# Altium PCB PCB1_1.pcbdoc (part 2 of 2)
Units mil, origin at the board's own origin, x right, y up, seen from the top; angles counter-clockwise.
Board outline 2576.88 x 4443.16 mil, 6 copper layers (Top Layer, Inner1, Inner2, Inner3, Inner4, Bottom Layer); 86 components, 97 nets, 400 pads, 188 vias.
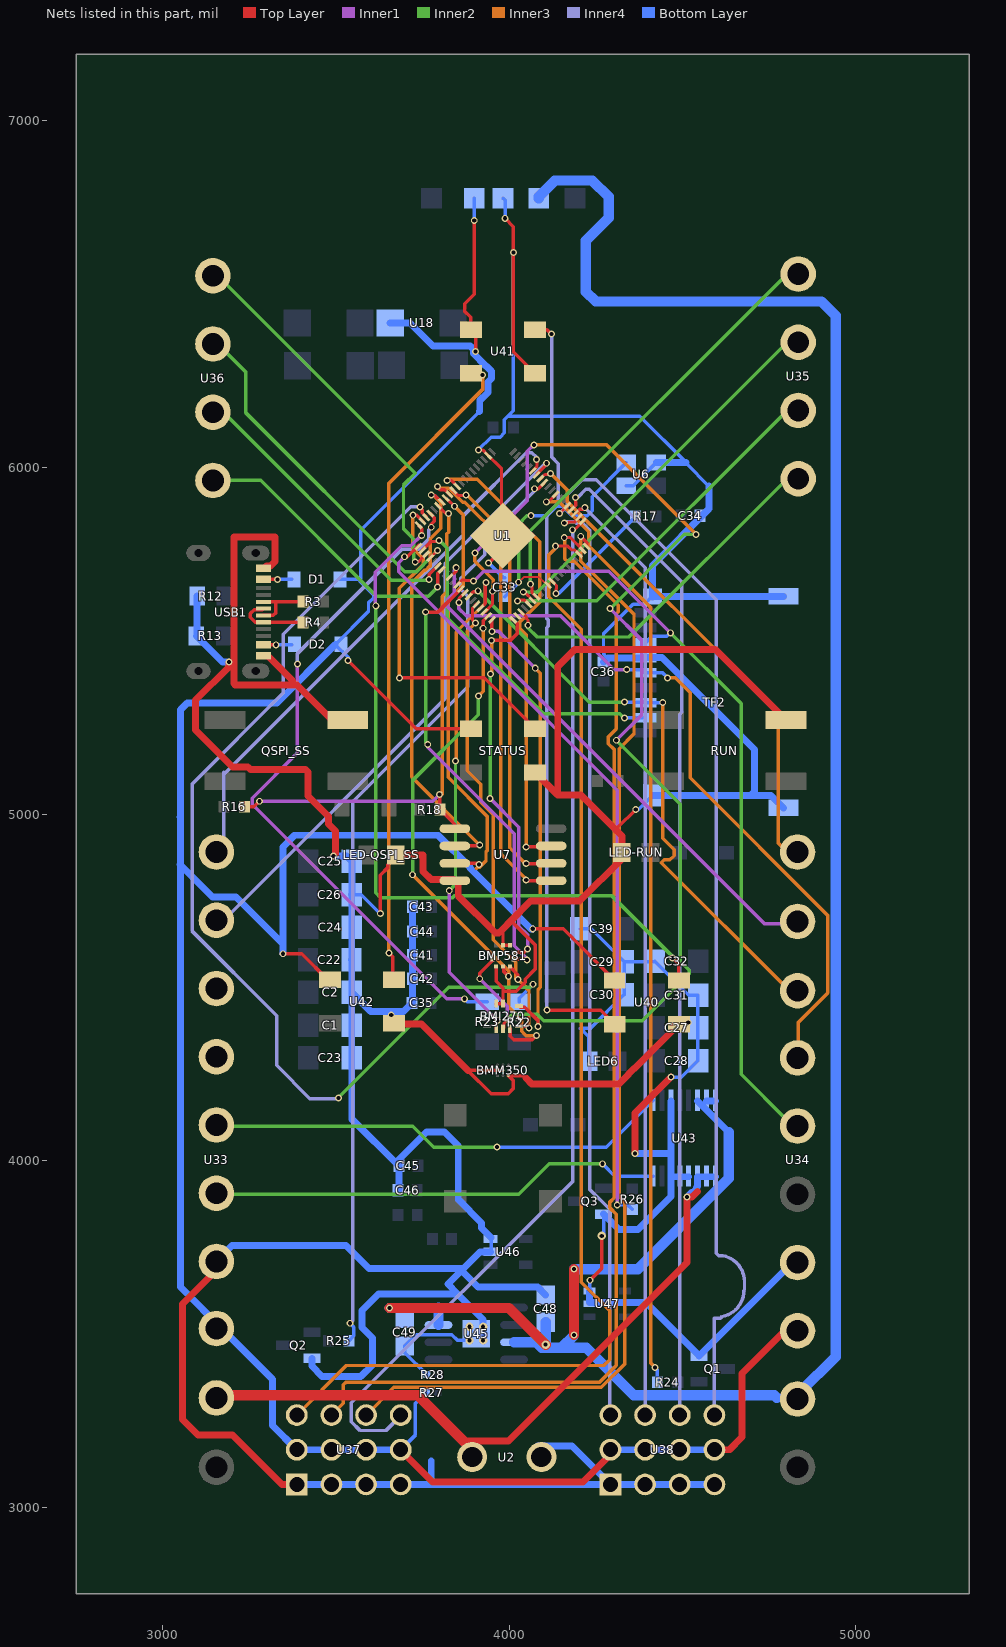
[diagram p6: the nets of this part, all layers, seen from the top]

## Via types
v1: diameter 20, hole 12.01, Top Layer to Bottom Layer, 175 vias
v2: diameter 24.02, hole 12.01, Top Layer to Bottom Layer, 8 vias
v3: diameter 24, hole 12, Top Layer to Bottom Layer, 4 vias
v4: diameter 20, hole 12, Top Layer to Bottom Layer, 1 vias

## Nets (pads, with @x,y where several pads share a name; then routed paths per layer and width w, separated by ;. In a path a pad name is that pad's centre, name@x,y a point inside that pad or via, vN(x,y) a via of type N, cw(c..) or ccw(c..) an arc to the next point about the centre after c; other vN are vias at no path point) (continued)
$5N18524: U40.2 U41.4 | length 2242.1
  Top Layer w10: U41.4@4073.4,6398.16 4108.78,6398.16 v1(4121.96,6384.98) ; v1(4108.42,4434.56) 4263.97,4434.56 U40.2@4304.36,4394.17
  Inner4 w10: v1(4108.42,4434.56) 4108.42,5538.19 4111.88,5541.64 4111.88,5560.68 4108.42,5564.14 4108.42,5863.22 4141.88,5896.67 4141.88,6010.91 4121.96,6030.83 v1(4121.96,6384.98)
$5N18586: U41.2 U42.4 | length 1863.2
  Top Layer w10: v1(3652.88,4599.16) 3663.4,4588.64 U42.4@3663.4,4520.16
  Inner3 w10: v1(3652.88,4599.16) 3652.88,5955.16 3922.88,6225.16 v1(3922.88,6267.16)
$5N24177: D1.2 USB1.2 | length 81.7
  Top Layer w10: USB1.2@3290.39,5677.65 3330.4,5677.65 v1(3330.88,5677.16)
  Bottom Layer w10: v1(3330.88,5677.16) D1.2@3371.89,5677.16
$5N24251: D2.2 USB1.11 | length 79.9
  Top Layer w10: USB1.11@3290.39,5488.67 v1(3327.29,5488.67)
  Bottom Layer w10: v1@3328.88,5489.16 D2.2@3371.89,5489.16
+5V: D1.1 D2.1 pad.4 R27.2 STATUS.1 U18.2 U33.3 U34.8 U37.2 U37.5 U37.8 U37.11 U38.2 U38.5 U38.8 U38.11 U40.1 U41.1 U42.1 | length 9155
  Top Layer w10: v1(3346.88,4597.16) 3401.36,4597.16 U42.1@3478.36,4520.16 ; v1(3534.88,5443.16) 3731.89,5246.16 STATUS.1@3889.36,5246.16 ; v1(3898.88,6713.16) 3898.88,6499.69 3871.88,6472.68 3871.88,6450.17 3888.36,6433.68 3888.36,6398.16 3902.89,6383.63 v1(3902.89,6334.61) ; v1(4067.84,4669.16) 4155.36,4669.16 U40.1@4304.36,4520.16
  Top Layer w20: U37.11@3686.88,3148.16 3703.88,3148.16 3778.88,3073.16 4213.17,3073.16 4291.88,3151.88 U38.2@4291.88,3180.16 ; U38.11@4591.88,3166.16 4634.88,3166.16 4671.88,3203.16 4671.88,3385.76 U34.8@4801.88,3515.76
  Bottom Layer w10: D1.1@3511.98,5677.21 3563.83,5677.21 3571.88,5669.16 ; v1(3534.88,5443.16) 3534.88,5452.15 3497.88,5489.16 3593.9,5585.18 3593.9,5609.85 3608.88,5624.84 3608.88,5632.15 3571.88,5669.16 ; U37.11@3686.88,3166.16 3729.36,3208.64 3729.36,3300.68 R27.2@3759.84,3331.16 ; v1@3898.31,6333.09 3901.36,6333.09 v1(3902.89,6334.61) ; v1(3898.88,6713.16) pad.4@3898.88,6777.16 ; 3913.43,6161.16 3571.88,5819.6 3571.88,5669.16
  Bottom Layer w20: 3049.72,4854.74 3050.88,4853.58 ; 3049.72,4991.77 3050.88,4992.93 ; v1(3346.88,4597.16) 3346.88,4625.58 ; D2.1@3497.88,5489.16 3329.88,5321.16 3070.88,5321.16 3050.88,5301.16 3050.88,4992.93 ; U18.2@3656.33,6417.16 3713.43,6417.16 3780.08,6350.52 3887.42,6350.52 3896.79,6341.15 v1@3896.79,6334.61 ; U37.11@3686.88,3166.16 U37.8@3586.88,3166.16 U37.5@3486.88,3166.16 U37.2@3386.88,3166.16 3316.88,3236.16 3316.88,3369.46 3176.88,3509.46 3050.88,3635.46 3050.88,4853.58 ; v1@3896.79,6328.51 3932.16,6293.15 3933.65,6293.15 3948.87,6277.92 3948.87,6256.4 3938.79,6246.32 3938.79,6217.07 3914.88,6193.16 3914.88,6162.61 3913.43,6161.16 ; v1(4067.84,4669.16) 4062.14,4669.16 3886.9,4844.4 3886.9,4847.15 3794.88,4939.16 3380.88,4939.16 3346.88,4905.16 3346.88,4625.58 ; U38.2@4291.88,3166.16 U38.5@4391.88,3166.16 U38.8@4491.88,3166.16 U38.11@4591.88,3166.16 ; 3050.88,4853.58 3143.59,4760.87 3211.59,4760.87 3346.88,4625.58 ; 3050.88,4853.58 3050.88,4992.93
ADC0: R24.1 U1.49 | length 2731.5
  Top Layer w9: v1(4106.88,5901.16) 4113.29,5901.16 U1.49@4135.21,5923.08
  Inner3 w10: v1(4106.88,5901.16) 4143.4,5901.16 4229.21,5815.35 4229.21,5774.84 4408.88,5595.16 4408.88,3415.16 v1(4420.88,3403.16)
  Bottom Layer w10: v1(4420.88,3403.16) 4427.22,3396.82 R24.1@4427.22,3361.16
ADC1: R25.1 U1.52 | length 2743.5
  Top Layer w9: v1(4073.25,5938.79) 4084.11,5938.79 U1.52@4101.8,5956.48
  Inner4 w10: v1(3540.88,3531.16) 3547.89,3538.17 3547.89,5035.75 3879.88,5367.73 3879.88,5629.05 3860.41,5648.52 3860.41,5680.03 3928.87,5748.49 3928.87,5788.41 v1@4079.25,5938.79
  Bottom Layer w10: R25.1@3537.85,3480.64 3551.85,3494.64 3551.85,3520.19 v1(3540.88,3531.16)
ADC2: U1.53 U34.1 | length 1410.2
  Top Layer w9: U1.53@4090.67,5967.62 4102.83,5979.79 4115.51,5979.79 v1(4118.88,5983.16)
  Inner3 w10: v1(4118.88,5983.16) 4167.89,5934.15 4167.89,5901.84 4775.78,5293.95 4775.78,4916.66 U34.1@4801.88,4890.56
ADC3: U1.54 U33.9 | length 1752.8
  Top Layer w9: U1.54@4079.53,5980.76 4107.89,6009.12 v1@4107.89,6014.38
  Inner4 w10: U33.9@3172.88,4690.56 3815.88,5333.56 3815.88,5724.37 v1@4103.89,6012.38
  other v1: 4107.89,6012.38
ADC4: U1.55 U33.10 | length 1582.5
  Top Layer w9: U1.55@4068.39,5991.89 4080.56,6004.07 4080.56,6013.77 4078.98,6015.35 v1@4078.98,6025.26
  Inner4 w10: U33.10@3176.88,4896.56 3176.88,5115.48 ; 3176.88,5121.48 3176.88,5115.48 ; 3867.87,5806.47 3176.88,5115.48 ; 3867.87,5812.47 3867.87,5861.63 4049.5,6043.26 4064.98,6043.26 v1@4078.98,6029.26
  other v1: 4078.98,6023.26
BUZ: R26.1 U1.1 | length 2242.8
  Top Layer w10: v1(3697.83,5742.73) 3705.88,5742.73 U1.1@3739.47,5776.33
  Inner1 w10: v1(3697.83,5742.73) 3680.88,5725.79 3680.88,5699.16 4311.58,5068.46 v1(4311.58,3872.38)
  Bottom Layer w10: v1(4311.58,3872.38) 4342,3872.38 R26.1@4354.88,3859.5
CLK: TF2.5 U1.13 U34.4 | length 2080.7
  Top Layer w9: v1@3854.88,5612.28 3854.88,5622.48 U1.13@3873.1,5640.7
  Inner1 w10: v1(3854.88,5610.28) 3854.88,5592.83 3875.57,5572.15 4147.9,5572.15 4302.88,5417.16 v1(4338.88,5417.16)
  Inner3 w10: v1(4456.88,5393.16) 4478.88,5393.16 4521.87,5350.18 4521.87,5104.66 4918.88,4707.64 4918.88,4483.94 4833.88,4398.94 U34.4@4833.88,4290.01
  Bottom Layer w10: v1(4338.88,5417.16) 4383.72,5417.16 TF2.5@4393.07,5407.81 4442.23,5407.81 v1(4456.88,5393.16)
CS: U1.9 U34.2 | length 1492.4
  Top Layer w10: 3840.73,5695.41 3846.88,5701.56 v1(3846.88,5711.16)
  Inner1 w10: v1@3846.88,5709.16 3840.88,5703.16 3840.88,5638.04 3821.89,5619.05 3821.89,5598.15 4736.34,4683.71 U34.2@4795.88,4683.71
GND: BMI270.6 BMI270.7 BMM350.B1 BMM350.B2 BMM350.C3 BMP581.3 BMP581.8 BMP581.9 C1.1 C2.1 C22.1 C23.1 C24.1 C25.1 C26.1 C27.1 C28.1 C29.1 C30.1 C31.1 C32.2 C33.1 C34.1 C35.2 C36.1 C39.2 C41.2 C42.1 C43.2 C44.1 C45.2 C46.1 C48.2 C49.2 LED6.2 LED-QSPI_SS.2 LED-RUN.2 pad.3 Q1.2 Q2.2 Q3.2 QSPI_SS.2 R12.2 R13.2 R28.2 RUN.2 STATUS.3 TF2.6 TF2.10 TF2.11 TF2.12 TF2.13 U1.62 U1.81 U2.2 U6.2 U6.4 U7.4 U33.4 U34.7 U37.1 U37.4 U37.7 U37.10 U38.1 U38.4 U38.7 U38.10 U40.3 U41.3 U42.3 U43.4 U43.5 U43.6 U43.11 U45.9 U46.2 U46.3 U47.2 U47.3 USB1.1 USB1.12 | length 21390.6
  Top Layer w9: v1(3910.88,6051.16) 3923.19,6051.16 U1.62@3935.22,6039.13 ; U1.62@3934.61,6039.13 U1.62@3935.22,6039.13 ; U1.81@3977.88,5809.16 3977.88,5996.47 U1.62@3935.22,6039.13
  Top Layer w10: v1(3627.88,4713.16) 3627.88,4823.99 3650.03,4846.14 3650.03,4854.3 3672.6,4876.87 LED-QSPI_SS.2@3672.6,4882.49 ; v1(3940.34,5724.61) 3981.88,5766.16 U1.81@3981.88,5803.16 ; BMI270.7@3962.19,4453.38 BMI270.6@3981.88,4453.38 3981.88,4488.49 ; BMP581.3@3962.2,4560.45 3962.2,4517.85 3981.88,4498.16 3981.88,4488.49 ; BMM350.B2@3981.88,4261.16 BMM350.B1@3966.13,4261.16 3882.19,4261.16 3881,4259.97 3947.81,4193.16 3996.88,4193.16 4010.88,4207.16 4010.88,4232.16 BMM350.C3@3997.63,4245.41 BMM350.C3@3997.22,4245.83 ; 3981.89,4669.18 BMP581.9@3981.89,4621.87 BMP581.8@4001.57,4621.87 ; v1(3987.88,6719.16) 4011.88,6695.16 v1(4011.88,6620.84) 4011.88,6333.69 U41.3@4073.4,6272.17 ; BMM350.C3@3998.46,4245.41 4040.63,4245.41 4047.88,4238.16 ; 4005.09,4692.38 4074.88,4622.58 4074.88,4553.16 4045.87,4524.15 4045.87,4514.47 4019.89,4488.49 3981.88,4488.49 ; v1(4232.88,3655.16) 4266.89,3689.17 v2(4266.89,3783.16) ; 4300.2,4961.84 4313.57,4961.84 v1(4364.88,5013.16)
  Top Layer w20: U33.4@3176.88,3706.31 3056.88,3586.31 3056.88,3253.16 3101.88,3208.16 3201.88,3208.16 3343.88,3066.16 U37.1@3386.88,3066.16 ; v1(3190.88,5439.16) 3190.88,5425.16 3094.88,5329.16 3094.88,5243.16 3201.89,5136.16 3245.39,5136.16 3253.32,5128.23 3411.81,5128.23 3418.88,5121.16 3418.88,5052.67 3478.88,4992.67 3478.88,4971.16 3498.88,4951.16 3498.88,4885.16 v1(3492.88,4879.16) ; USB1.12@3290.39,5457.18 3303.05,5457.18 3374.56,5385.66 3374.56,5373 ; USB1.1@3290.39,5709.15 3291.39,5708.15 3299.04,5715.8 3311.52,5715.8 3324.09,5728.37 3324.09,5799.95 3205.67,5799.95 3205.67,5376.37 3209.04,5373 3374.56,5373 ; QSPI_SS.2@3534.05,5271.74 3488.3,5271.74 3387.04,5373 3374.56,5373 ; U42.3@3663.4,4394.17 3746.81,4394.17 3881,4259.97 ; LED-QSPI_SS.2@3672.6,4882.49 3750.94,4882.49 3750.94,4835.11 3774.88,4811.16 U7.4@3839.9,4811.16 ; U7.4@3842.9,4808.16 3852.87,4798.2 3852.87,4764.47 3960.89,4656.45 3969.16,4656.45 3981.89,4669.18 4005.09,4692.38 4061.87,4749.16 4202.88,4749.16 4324.9,4871.17 4324.9,4937.15 4300.2,4961.84 4207.37,5054.68 4139.89,5054.68 ; U1.81@3971.88,5803.16 U1.81@3976.88,5808.16 ; 4047.88,4238.16 4064.88,4221.16 4316.4,4221.16 4344.1,4248.86 4344.1,4250.86 4359.32,4266.08 4361.32,4266.08 U40.3@4489.4,4394.17 U40.3@4489.4,4396.17 ; STATUS.3@4074.4,5120.17 4139.89,5054.68 ; v1(4362.88,4021.16) 4362.88,4137.16 v1(4466.88,4241.16) ; RUN.2@4799.05,5271.74 4595.63,5475.16 4188.88,5475.16 4139.89,5426.17 4139.89,5054.68
  Bottom Layer w10: C26.1@3545.21,4767.96 3573.08,4767.96 v1(3627.88,4713.16) ; R28.2@3761.84,3383.16 3698.88,3446.12 C49.2@3698.88,3465.79 3731.54,3498.44 3833.91,3498.44 3850.89,3481.47 v3(3885.2,3481.47) ; v1(3910.88,6051.16) 3947.64,6087.91 3973.49,6087.91 3985.52,6099.95 3985.52,6137.46 3995.88,6147.82 ; v3(3924.57,3481.47) v3(3924.57,3520.84) ; v1(3940.34,5724.61) 3982.23,5682.72 C33.1@3986.88,5682.72 ; U46.2@3947.7,3741.16 U46.3@3947.7,3778.56 ; pad.3@3981.88,6777.16 3987.88,6771.16 v1(3987.88,6719.16) ; v1(4011.88,6620.84) 4011.88,6163.82 3995.88,6147.82 ; C39.2@4204.78,4669.11 4236.54,4669.11 C29.1@4331.23,4574.41 ; LED6.2@4229.53,4287.16 4229.53,4357.56 4204.22,4382.88 4235.23,4382.88 C30.1@4330.77,4478.41 4331.23,4478.87 C29.1@4331.23,4574.41 ; U47.3@4231.7,3626.57 4231.7,3653.98 v1(4232.88,3655.16) ; v2(4266.89,3783.16) 4272.25,3788.52 Q3.2@4272.25,3845.76 ; C36.1@4278.93,5445.76 4278.93,5455.76 4271.86,5462.84 4271.86,5520.64 4357.02,5605.8 4390.39,5605.8 TF2.10@4412.75,5628.16 ; U6.2@4337.57,5947.7 4357.26,5947.7 U6.4@4424.19,6014.63 ; v1(4364.88,5013.16) 4372.43,5013.16 TF2.13@4412.75,5053.48 ; v1(4466.88,4241.16) 4496.79,4241.16 4543.58,4287.96 4543.58,4383.16 4543.58,4477.16 4518.18,4477.16 C32.2@4420.18,4575.16 4419.44,4574.41 C29.1@4331.23,4574.41 ; 4510.12,6012.63 4576.11,5946.63 ; 4510.12,6014.63 4376.92,6147.82 3995.88,6147.82
  Bottom Layer w20: R12.2@3099.51,5629.16 3099.51,5516.57 R13.2@3097.19,5514.25 3172.28,5439.16 v1(3190.88,5439.16) ; U33.4@3154.88,3709.46 3200.59,3755.16 3528.88,3755.16 3595.08,3688.96 3867.92,3688.96 ; U37.1@3386.88,3066.16 U37.4@3486.88,3066.16 U37.7@3586.88,3066.16 U37.10@3686.88,3066.16 3774.98,3066.16 ; Q2.2@3430.25,3429.76 3430.25,3407.76 3460.25,3377.76 3571.48,3377.76 3604.88,3411.16 3604.88,3488.82 3574.88,3518.82 3574.88,3567.5 3622.81,3615.43 3851.12,3615.43 ; v1(3492.88,4879.16) 3530.46,4879.16 C25.1@3545.66,4863.96 3545.66,4768.41 C26.1@3545.21,4767.96 3545.58,4767.58 C24.1@3545.58,4673.16 3545.58,4580.51 C22.1@3545.03,4579.96 3545.49,4579.5 C2.1@3545.49,4485.96 ; C46.1@3679.32,3915.16 3681.32,3917.16 C45.2@3681.32,3985.16 ; C43.2@3720.6,4732.6 3721.32,4731.87 C44.1@3721.32,4661.16 C41.2@3721.32,4593.16 C42.1@3721.32,4525.16 3721.32,4457.16 3695.32,4431.16 3600.29,4431.16 C2.1@3545.49,4485.96 ; 3774.88,3133.5 3774.88,3066.26 3774.98,3066.16 ; v3(3924.57,3520.84) 3924.57,3541.97 3851.12,3615.43 ; U46.2@3945.7,3737.16 3916.11,3737.16 3867.92,3688.96 ; U46.3@3947.7,3778.56 3919.99,3806.28 3919.99,3820.93 3852.88,3888.03 3852.88,4043.16 3812.88,4083.16 3761.32,4083.16 3681.32,4003.16 C45.2@3681.32,3985.16 ; U2.2@4081.88,3177.16 4180.88,3177.16 U38.1@4291.88,3066.16 ; C48.2@4104.88,3612.53 4082.25,3635.16 3910.3,3635.16 3862.21,3683.25 ; U47.3@4231.7,3624.56 4231.7,3591.16 4394.92,3591.16 Q1.2@4547.51,3438.56 ; C36.1@4271.86,5438.69 4278.93,5445.76 4284.29,5451.12 TF2.6@4393.07,5451.12 4394.52,5452.57 4441.11,5452.57 4707.56,5186.13 4707.56,5065.48 4695.56,5053.48 ; Q3.2@4272.25,3845.76 4316.85,3801.16 4370.88,3801.16 4466.49,3896.77 U43.6@4466.49,3953.71 ; v1(4362.88,4021.16) 4465.69,4021.16 4466.49,4021.96 ; TF2.13@4412.75,5053.48 4695.56,5053.48 ; TF2.10@4412.75,5626.16 TF2.10@4412.75,5628.16 ; U6.4@4424.19,6014.63 4510.12,6014.63 ; U43.11@4466.49,4172.61 4466.49,4021.96 ; U43.4@4517.68,3953.71 4492.08,3953.71 U43.6@4466.49,3953.71 ; Q1.2@4547.51,3436.56 4801.88,3690.93 U34.7@4801.88,3709.46 ; 4576.11,5946.63 4576.11,5881.14 4412.75,5717.77 TF2.10@4412.75,5628.16 ; U38.10@4591.88,3066.16 U38.7@4491.88,3066.16 U38.4@4391.88,3066.16 U38.1@4291.88,3066.16 ; TF2.12@4790.7,5018.04 4755.26,5053.48 4695.56,5053.48 ; TF2.11@4790.7,5628.28 4790.58,5628.16 TF2.10@4412.75,5628.16 ; C2.1@3545.49,4485.96 3545.49,4391.25 C1.1@3545.58,4391.16 C23.1@3545.58,4297.16 3545.58,4120.9 C45.2@3681.32,3985.16 ; 3774.98,3066.16 U38.1@4291.88,3066.16 ; 3851.12,3615.43 3822.75,3643.79 3862.21,3683.25 ; 3862.21,3683.25 3867.92,3688.96 ; U43.6@4466.49,3953.71 4466.49,4021.96
  other v1: 4516.35,4398.66 3659.47,4420.81
  other v3: 3885.2,3520.84
GPIO0: R23.1 U1.77 | length 2004.3
  Top Layer w10: U1.77@3771.88,5867.4 3784.05,5855.24 3784.05,5845.52 3774.88,5836.35 v1(3774.88,5827.72)
  Inner1 w10: v1(3388.88,5433.16) 3388.88,5176.84 3257.9,5045.85 3257.9,5028.47 3819.21,4467.16 v1(3870.88,4467.16)
  Inner4 w10: v1(3388.88,5433.16) 3388.88,5463.47 3689.13,5763.72 3737.02,5763.72 3768.28,5794.98 3768.28,5821.12 v1(3774.88,5827.72)
  Bottom Layer w10: v1(3870.88,4467.16) 3878.67,4459.38 R23.1@3936.54,4459.38
GPIO1: R22.1 U1.78 | length 3023
  Top Layer w9: v1(3742.88,5886.55) 3742.88,5884.55 3749.08,5878.35 3749.08,5868.93 U1.78@3761.75,5856.26
  Inner2 w10: v1(3506.88,4181.16) 3825.89,4500.17 4059.89,4500.17 v1(4068.88,4509.16)
  Inner4 w10: v1(3506.88,4181.16) 3504.88,4179.16 3424.88,4179.16 3328.88,4275.16 3328.88,4418.65 3084.72,4662.81 3084.72,5086.3 3348.27,5349.85 3348.27,5518.74 3716.08,5886.55 v1(3742.88,5886.55)
  Bottom Layer w10: R22.1@4028.95,4458.08 4028.95,4469.23 v1(4068.88,4509.16)
GPIO6: U1.3 U36.4 | length 1131.2
  Top Layer w9: v1@3728.79,5729.15 3738.84,5729.15 U1.3@3761.75,5752.06
  Inner2 w10: U36.4@3158.88,6553.44 3728.79,5983.54 3694.88,5949.64 3694.88,5823.57 3724.79,5793.67 v1@3724.79,5727.15
  other v1: 3728.79,5727.15
GPIO7: U1.4 U36.3 | length 1008.1
  Top Layer w9: U1.4@3770.88,5738.92 3792.88,5760.92 v1(3792.88,5761.16)
  Inner2 w10: U36.3@3176.88,6338.58 3239.05,6276.42 3239.05,6159 3698.83,5699.21 3733.36,5699.21 3751.78,5717.63 3751.78,5720.05 v1(3792.88,5761.16)
GPIO8: U1.6 U36.2 | length 841.6
  Top Layer w10: v1@3768.88,5679.16 3768.88,5691.77 U1.6@3795.15,5718.04
  Inner2 w10: U36.2@3176.88,6157.73 3659.45,5675.16 v1@3768.88,5675.16
  other v1: 3768.88,5677.16
GPIO9: U1.7 U36.1 | length 821.6
  Top Layer w10: v4@3792.88,5657.16 v4@3794.12,5658.4 ; 3793.75,5693.36 3793.12,5692.74 3793.12,5659.4 v4@3794.12,5658.4 ; v4@3794.12,5656.4 v4@3794.12,5658.4 ; 3794.12,5694.74 U1.7@3806.29,5706.9
  Inner2 w10: U36.1@3176.88,5962.88 3283.16,5962.88 3616.88,5629.16 3766.88,5629.16 v4(3792.88,5655.16)
GPIO13: BMP581.6 U1.12 | length 1293.8
  Top Layer w10: v1(3758.88,5583.16) 3794.29,5583.16 U1.12@3860.97,5649.84 ; BMP581.6@4012.59,4581.32 4048.72,4581.32 v1(4050.88,4579.16)
  Inner1 w10: v1(3764.88,5201.16) 3764.88,5192.65 4013.88,4943.65 4013.88,4620.48 4050.88,4583.48 v1(4050.88,4579.16)
  Inner2 w10: v1(3758.88,5583.16) 3758.88,5207.16 v1(3764.88,5201.16)
GPIO16: BMI270.1 BMP581.5 U1.16 | length 1389.7
  Top Layer w9: v1(3902.37,5551.16) 3893.84,5559.69 3893.84,5594.02 U1.16@3906.51,5606.68
  Top Layer w10: BMP581.5@4001.57,4560.45 4024.88,4537.13 v1(4024.88,4523.16) ; BMI270.1@4027.95,4387.64 4052.34,4387.64 v1(4056.95,4383.03)
  Inner3 w10: v1(3902.37,5551.16) 3878.37,5527.16 3878.37,5125.5 3917.89,5085.97 3917.89,5033.97 3953.88,4997.99 3953.88,4638.17 4018.88,4573.16 v1@4018.88,4525.16 ; v1(4024.88,4523.16) 4056.95,4491.1 v1(4056.95,4383.03)
GPIO17: BMI270.12 U1.17 | length 1470.1
  Top Layer w9: U1.17@3915.64,5592.16 3930.79,5607.31 v1@3930.79,5666
  Top Layer w10: BMI270.12@3962.19,4380.94 3962.19,4393.91 3965.87,4397.59 v1(3965.87,4405.16)
  Inner1 w10: v1(3826.88,4779.16) 3826.88,4544.15 v1(3965.87,4405.16)
  Inner2 w10: v1(3826.88,4779.16) 3844.88,4797.16 v1(3844.88,5153.16)
  Inner3 w9: v1@3842.88,5153.16 3846.88,5157.16 3846.88,5525.35 3930.79,5609.26 v1@3930.79,5668
  other v1: 3932.79,5668
GPIO18: BMI270.13 BMP581.2 U1.18 | length 3554.1
  Top Layer w9: U1.18@3928.78,5583.02 3951.63,5605.87 v1(3951.63,5643.16) ; BMI270.13@3981.88,4380.94 3985.26,4384.32 3985.26,4397.3 3994.47,4406.51 v1(3994.47,4409.16)
  Top Layer w10: v1(3914.88,4525.16) 3914.88,4540.48 3951.18,4576.78 BMP581.2@3951.18,4581.32
  Inner1 w10: v1(3900.88,5753.16) 4052.27,5904.55 4052.27,6046.55 v1(4070.88,6065.16) ; v1(3914.88,4525.16) 3994.47,4445.58 v1(3994.47,4409.16) ; v1(4290.88,5593.16) 4382.88,5501.16 4382.88,5287.16 v1(4308.88,5213.16)
  Inner2 w10: v1(3994.47,4409.16) 4008.46,4423.16 4080.15,4423.16 4099.73,4403.58 4383.3,4403.58 4518.88,4539.16 4518.88,4549.16 4493.87,4574.18 4493.87,5028.18 v1(4308.88,5213.16) ; v1(4290.88,5593.16) 4504.88,5807.16 v1(4538.88,5807.16)
  Inner3 w10: v1(3900.88,5753.16) 3900.88,5729.58 3953.78,5676.69 3953.78,5659.31 3951.63,5657.16 v1(3951.63,5643.16) ; v1(4070.88,6065.16) 4280.88,6065.16 v1(4538.88,5807.16)
GPIO19: BMI270.14 BMP581.4 U1.19 | length 1611.5
  Top Layer w9: v1(3924.78,5536.28) 3924.78,5558.14 3939.92,5573.27 U1.19@3939.92,5573.89
  Top Layer w10: BMP581.4@3981.89,4560.45 3984.68,4557.66 3984.68,4545.37 v1(3997.93,4532.11) ; BMI270.14@4001.56,4380.94 4002.88,4379.62 4002.88,4359.16 4012.88,4349.16 4066.29,4349.16 v1(4078.42,4361.29)
  Inner2 w10: v1(3720.88,4825.16) 3720.88,5097.16 3910.88,5287.16 v1(3910.88,5341.16)
  Inner3 w10: v1(3720.88,4825.16) 3997.93,4548.11 v1(3997.93,4532.11) 3997.93,4443.92 4035.96,4405.89 4035.96,4373.34 4048.25,4361.04 4065.64,4361.04 4065.88,4361.29 v1(4078.42,4361.29) ; v1(3910.88,5341.16) 3924.88,5355.16 3924.88,5413.24 3924.78,5413.35 v1(3924.78,5536.28)
GPIO20: BMI270.4 U1.20 | length 1336
  Top Layer w10: v1(3949.9,5527.15) 3949.9,5559.6 U1.20@3951.05,5560.75 ; BMI270.4@4027.95,4446.7 4031.34,4443.31 4044.31,4443.31 4082.88,4404.73 v1(4082.88,4387.16)
  Inner1 w10: v1(3949.9,5527.15) 3968.9,5527.15 v1(4074.88,5421.16)
  Inner3 w10: v1(4074.88,5421.16) 4089.87,5406.18 4089.87,4500.47 4082.88,4493.48 v1(4082.88,4387.16)
GPIO21: BMP581.7 U1.21 | length 1107.4
  Top Layer w10: v1(3948.88,5501.16) 4002.88,5501.16 4022.88,5521.16 4022.88,5549.58 U1.21@4011.71,5560.75 ; BMP581.7@4012.59,4601 4042.72,4601 v1(4052.88,4611.16)
  Inner1 w10: v1(3944.88,5045.16) 4027.9,4962.15 4027.9,4676.47 4052.88,4651.48 v1(4052.88,4611.16)
  Inner2 w10: v1(3944.88,5045.16) 3944.88,5403.57 v1(3945.84,5404.53)
  Inner3 w10: v1(3945.84,5404.53) 3948.88,5407.57 v1(3948.88,5501.16)
GPIO22: U1.22
GPIO23: U1.23 U35.4 | length 1001.1
  Top Layer w9: U1.23@4034.99,5583.02 4048.87,5569.14 4048.87,5565.14 4053.89,5560.12 v1(4053.89,5545.02)
  Inner2 w10: v1(4053.89,5545.02) 4053.89,5538.15 4080.88,5511.16 4345.16,5511.16 U35.4@4801.88,5967.88
GPIO24: U1.25 U35.3 | length 1046
  Top Layer w9: v1(4023.32,5615.31) 4025.47,5617.46 4044.48,5617.46 4056.65,5605.3 U1.25@4057.26,5605.3
  Inner2 w10: v1(4023.32,5615.31) 4252.45,5615.31 U35.3@4801.88,6164.74
GPIO25: U1.26 U35.2 | length 1097.9
  Top Layer w9: v1(4040.53,5640.52) 4044.3,5640.52 U1.26@4068.39,5616.43
  Inner2 w10: v1(4040.53,5640.52) 4080.81,5640.52 U35.2@4801.88,6361.59
GPIO26: U1.27 U35.1 | length 1245.5
  Top Layer w9: v1@4058.88,5663.51 4065.36,5657.03 4065.36,5639.73 U1.27@4077.53,5627.57
  Inner2 w10: v1(4060.88,5663.51) 4060.88,5817.44 U35.1@4801.88,6558.44
MISO: TF2.7 U1.11 U34.5 | length 2348.3
  Top Layer w9: U1.11@3850.83,5662.98 3862.99,5675.14 3872.71,5675.14 3873.44,5674.42 v1@3897.27,5674.42
  Inner1 w10: v1(3897.27,5672.42) 3926.01,5701.16 4286.88,5701.16 v1(4464.88,5523.16)
  Inner2 w10: v1(4464.88,5523.16) 4668.88,5319.16 4668.88,4249.16 4801.88,4116.16 U34.5@4801.88,4103.16
  Bottom Layer w10: TF2.7@4393.07,5494.42 4411.62,5512.97 4454.69,5512.97 v1(4464.88,5523.16)
MOSI: TF2.3 U1.14 U34.3 | length 1714.3
  Top Layer w9: U1.14@3884.24,5629.57 3896.41,5641.73 3905.01,5641.73 v1@3909.66,5646.38
  Inner2 w10: v1(3909.66,5644.38) 4230.88,5323.16 v1(4332.88,5323.16)
  Inner3 w10: v1(4442.9,5322.26) 4442.9,4930.74 4475.87,4897.77 4475.87,4880.39 4463.58,4868.1 4447.12,4868.1 4438.88,4859.86 U34.3@4801.88,4496.86
  Bottom Layer w10: v1(4332.88,5323.16) 4391.1,5323.16 TF2.3@4393.07,5321.19 4441.83,5321.19 v1(4442.9,5322.26)
NEOIN: U1.80 U40.4 | length 2147.9
  Top Layer w10: U1.80@3739.47,5831.99 3747.3,5824.17 v1@3747.3,5801.67 ; v1(4470.88,4585.16) 4489.4,4566.64 U40.4@4489.4,4520.16
  Inner1 w10: v1(3614.88,5601.16) 3612.88,5603.16 3612.88,5697.68 3689.36,5774.15 3715.78,5774.15 3745.3,5803.67 v1(3747.3,5803.67)
  Inner2 w10: v1@3614.88,5597.16 3614.88,4773.16 3629.87,4758.18 3835.58,4758.18 3842.56,4765.16 4294.88,4765.16 4470.88,4589.16 v1(4470.88,4585.16)
PISTA: STATUS.4 U1.79 | length 998.8
  Top Layer w9: v1(3721.83,5862.62) 3733.12,5862.62 U1.79@3750.61,5845.13
  Top Layer w10: v1(3682.88,5393.16) 3927.4,5393.16 STATUS.4@4074.4,5246.16
  Inner3 w10: v1(3682.88,5393.16) 3682.88,5651.5 3751.78,5720.39 3751.78,5736.68 3721.83,5766.63 v1(3721.83,5862.62)
PWM1: U1.38 U37.3 | length 3480.8
  Top Layer w9: v1(4133.41,5773.16) 4169.2,5773.16 4180.14,5762.22 4189.24,5762.22 4192.3,5759.16 4192.92,5759.16 U1.38@4202.02,5750.06
  Inner3 w10: U37.3@3386.88,3266.16 3529.88,3409.16 4272.88,3409.16 4289.87,3426.15 4289.87,3567.85 4207.87,3649.85 4207.87,5533.7 4113.9,5627.67 4113.9,5747.85 4133.41,5767.36 v1(4133.41,5773.16)
  Inner4 w10: U37.3@3390.88,3266.16 3391.88,3265.16 U37.3@3395.88,3265.16
PWM2: U1.39 U37.6 | length 3477.9
  Top Layer w9: v1(4158.71,5797.67) 4176.68,5797.67 U1.39@4213.16,5761.19
  Inner3 w10: U37.6@3486.88,3266.16 3520.88,3300.16 3520.88,3353.16 3527.96,3360.23 4259.96,3360.23 4308.88,3409.16 4308.88,3845.4 4290.6,3863.69 4290.6,3881.07 4302.89,3893.37 4302.89,5186.64 4285.89,5203.64 4285.89,5222.68 4308.88,5245.68 4308.88,5578.65 4313.88,5583.64 4313.88,5602.68 4187.4,5729.16 4166.88,5729.16 4159.81,5736.23 4159.81,5796.57 v1(4158.71,5797.67)
PWM3: U1.40 U37.9 | length 3319.9
  Top Layer w10: v1(4206.22,5801.67) 4224.29,5783.59 U1.40@4224.29,5772.33
  Inner3 w10: U37.9@3586.88,3266.16 3666.94,3346.22 4265.76,3346.22 4332.57,3413.02 4332.57,3881.07 4316.91,3896.73 4316.91,5188.67 4359.87,5231.63 4359.87,5576.51 4206.22,5730.17 v1(4206.22,5801.67)
PWM4: U1.42 U37.12 | length 3048
  Top Layer w9: v1(4182.49,5820.38) 4188.41,5820.38 U1.42@4213.16,5845.13
  Inner4 w10: U37.12@3686.88,3264.16 3644.4,3221.68 3569.29,3221.68 3544.4,3246.57 3544.4,3301.2 4183.22,3940.02 4183.22,5817.64 v1@4182.49,5818.38
PWM5: U1.43 U38.3 | length 2712.9
  Top Layer w9: v1(4158.84,5839.93) 4169.53,5839.93 4172.97,5843.37 4189.12,5843.37 U1.43@4202.02,5856.26
  Inner4 w10: v1@4156.84,5839.93 4160.28,5843.37 4190.02,5843.37 4193.45,5839.93 4210.12,5839.93 4232.88,5817.16 4232.88,3916.56 4289.88,3859.56 U38.3@4289.88,3266.16
PWM6: U1.44 U38.6 | length 2724.2
  Top Layer w9: U1.44@4190.88,5867.4 4203.05,5879.57 4213.29,5879.57 v1(4217.98,5884.26)
  Inner4 w10: v1(4217.98,5884.26) 4391.88,5710.36 U38.6@4391.88,3266.16
PWM7: U1.45 U38.9 | length 2872.9
  Top Layer w9: U1.45@4179.75,5878.54 4191.92,5890.71 4191.92,5900.41 4190.88,5901.45 v1(4190.88,5913.16)
  Inner4 w10: v1@4186.88,5913.16 v1(4190.88,5913.16) ; v1@4196.88,5913.16 4220.88,5937.16 4230.88,5937.16 4497.88,5670.17 4497.88,5293.64 4491.88,5287.64 4491.88,3268.17 U38.9@4493.88,3266.16
PWM8: U1.46 U38.12 | length 3138.6
  Top Layer w9: v1(4144.88,5867.16) 4155.23,5877.5 4156.45,5877.5 U1.46@4168.62,5889.67
  Inner4 w10: v1(4144.88,5867.16) 4167.89,5890.17 4167.89,5922.68 4210.37,5965.16 4250.88,5965.16 4596.88,5619.16 4596.88,3733.16 4604.2,3725.85 4615.88,3725.85 cw(c4602.88,3651.16) 4678.69,3651.16 4678.69,3627.16 4676.69,3625.16 cw(c4600.88,3625.16) 4613.88,3550.47 4609.35,3545.94 4591.88,3545.94 U38.12@4591.88,3266.16
QSPI_SCLK: U1.71 U7.6 | length 1251.4
  Top Layer w9: U1.71@3839.7,5932.22 3840.3,5932.22 3853.36,5919.16 v1@3874.88,5919.16
  Top Layer w10: v1(4048.88,4857.16) 4119.86,4857.16 U7.6@4120.86,4858.16
  Inner3 w10: v1@3876.88,5921.16 4000.88,5797.16 4000.88,4903.16 4046.88,4857.16 v1@4050.88,4857.16
  other v1: 3874.88,5921.16
QSPI_SD1: U1.74 U7.2 | length 1252
  Top Layer w9: v1@3774.88,5919.12 3786.59,5919.12 3806.29,5899.42 U1.74@3806.29,5898.81
  Top Layer w10: U7.2@3842.9,4908.16 3911.89,4908.16 v1(3914.89,4911.16)
  Inner3 w10: v1@3776.88,5925.12 3802.88,5899.11 3802.88,5825.16 3771.89,5794.17 3771.89,5714.68 3769.89,5714.68 3759.36,5704.15 3755.36,5704.15 3718.88,5667.68 3718.88,5107.17 v1@3910.89,4915.16
  other v1: 3774.88,5921.12
QSPI_SD2: U1.73 U7.3 | length 1242.4
  Top Layer w9: U1.73@3817.43,5911.94 3829.59,5899.78 3830.62,5899.78 v1(3842.02,5888.37)
  Top Layer w10: U7.3@3842.9,4858.16 3909.88,4858.16 v1(3912.88,4855.16)
  Inner3 w10: v1(3842.02,5888.37) 3867.87,5862.53 3867.87,5661.03 3823.9,5617.06 3823.9,5106.15 3935.88,4994.17 3935.88,4894.47 3932.88,4891.48 3932.88,4865.16 3914.88,4847.16 3908.88,4847.16 3904.88,4843.16
QSPI_SD3: U1.70 U7.7 | length 1365
  Top Layer w9: v1(3820.88,5963.16) 3833.01,5963.16 U1.70@3850.83,5945.35
  Top Layer w10: v1(4048.88,4905.65) 4118.35,4905.65 U7.7@4120.86,4908.16
  Inner3 w10: v1(3820.88,5963.16) 3824.14,5966.41 3907.72,5966.41 4087.88,5786.26 4087.88,5611.53 4030.9,5554.55 4030.9,5535.5 4048.88,5517.52 v1(4048.88,4905.65)
QSPI_SDO: U1.72 U7.5 | length 1376.6
  Top Layer w10: v1@3793.23,5943.2 3800.25,5936.17 3814.09,5936.17 U1.72@3828.56,5921.69 ; v1(4048.88,4809.92) 4050.64,4808.16 U7.5@4120.86,4808.16
  Inner3 w10: v1@3793.23,5947.2 3800.25,5940.17 3825.36,5940.17 3865.36,5900.17 3871.88,5900.17 3974.88,5797.16 3974.88,4885.92 v1@4048.88,4811.92
  other v1: 3793.23,5945.2
QSPI_SS: R16.2 R18.1 U1.75 U7.1 | length 1551
  Top Layer w9: U1.75@3795.15,5889.67 3817.66,5867.16 v1(3824.88,5867.16)
  Top Layer w10: R16.2@3236.54,5021.16 3262.88,5021.16 v1(3278.88,5037.16) ; v1(3798.88,5057.16) 3798.88,5014.82 R18.1@3800.54,5013.16 3842.9,4970.8 U7.1@3842.9,4958.16
  Inner1 w10: v1(3278.88,5037.16) 3778.88,5037.16 v1(3798.88,5057.16)
  Inner3 w10: v1@3806.88,5057.16 3806.88,5627.87 3819.88,5640.86 3819.88,5808.68 3824.88,5813.69 v1(3824.88,5867.16)
RPD+: R4.1 USB1.6 USB1.8 | length 212.9
  Top Layer w10: USB1.6@3290.39,5593.01 3287.59,5590.21 3264.19,5590.21 3252.88,5578.9 3252.88,5567.73 3266.98,5553.64 USB1.8@3290.39,5553.64 3404.75,5553.64 R4.1@3405.22,5553.16
RPD-: R3.1 USB1.5 USB1.7 | length 186.9
  Top Layer w10: USB1.7@3290.39,5573.32 3319.04,5573.32 3326.88,5581.16 3326.88,5612.76 3327.29,5613.16 ; USB1.5@3290.39,5612.69 3290.86,5613.16 3327.29,5613.16 ; R3.1@3405.22,5613.16 3327.29,5613.16
RX: U33.8
SCL: U33.6 U43.9 | length 1319.7
  Inner2 w10: U33.6@3176.88,4100.01 3721.71,4100.01 3782.56,4039.16 v1(3964.88,4039.16)
  Bottom Layer w10: v1(3964.88,4039.16) 4279.86,4039.16 U43.9@4415.31,4174.61
SDA: U33.5 U43.8 | length 1289.6
  Inner2 w10: U33.5@3176.88,3903.16 4027.21,3903.16 4115.21,3991.16 v1(4268.88,3991.16)
  Bottom Layer w10: v1(4268.88,3991.16) 4304.33,3955.71 U43.8@4415.31,3955.71
SDCS: TF2.2 U1.2 | length 983.9
  Top Layer w9: U1.2@3750.61,5763.19 3773.57,5786.15 3791.88,5786.15 v1@3796.88,5791.16
  Inner2 w10: v1(3796.88,5789.16) 3801.89,5784.15 3804.41,5784.15 3820.88,5767.68 3820.88,5567.16 4098.88,5289.16 4318.88,5289.16 4330.88,5277.16 v1(4332.88,5277.16)
  Bottom Layer w10: v1(4332.88,5277.16) 4333.61,5277.89 TF2.2@4393.07,5277.89
TX: U33.7
VCC: C48.1 C49.1 pad.2 U2.1 U33.2 U34.9 U43.1 U43.2 U43.3 U43.14 U43.15 U43.16 U45.3 U45.7 U45.8 | length 9163.6
  Top Layer w20: 3881.88,3191.16 3998.03,3191.16 4512.86,3705.99 v1(4512.86,3895.16) 4526.88,3895.16 4542.88,3911.16
  Top Layer w30: U33.2@3176.88,3312.61 3187.43,3323.16 3735.88,3323.16 U2.1@3881.88,3177.16 ; v1(3654.88,3575.16) 3999.13,3575.16 v2(4104.88,3469.41) ; v1(4186.88,3497.16) v1(4186.88,3687.16)
  Bottom Layer w20: v1(4512.86,3895.16) 4526.72,3909.02 4531.47,3909.02 4540.83,3918.38 4540.83,3923.13 4543.27,3925.57 4543.27,3953.71 U43.1@4594.45,3953.71 ; U43.14@4543.27,4172.61 4632.88,4083 ; U43.15@4568.86,4172.61 U43.16@4594.45,4172.61 ; 4771.88,3315.76 4791.88,3315.76 U34.9@4801.88,3315.76
  Bottom Layer w30: v1(3654.88,3575.16) 3794.86,3575.16 U45.8@3795.86,3576.16 U45.7@3795.86,3526.16 ; U45.3@4013.9,3476.16 4077.88,3476.16 4094.13,3459.92 4114.38,3459.92 ; pad.2@4084.88,6777.16 4084.88,6782.04 4130.99,6828.15 4239.9,6828.15 4286.88,6781.16 4286.88,6721.2 4220.6,6654.91 4220.6,6507.45 4248.88,6479.16 4900.88,6479.16 4941.57,6438.47 4941.57,3434.78 4838.55,3331.76 4807.88,3331.76 U34.9@4791.88,3315.76 ; C48.1@4104.88,3533.79 v2(4104.88,3469.41) 4114.38,3459.92 ; v1(4186.88,3497.16) 4149.64,3459.92 ; v1(4186.88,3687.16) 4370.88,3687.16 4632.88,3949.16 4632.88,4083 ; 4222.13,3459.92 4149.64,3459.92 ; 4222.88,3459.16 4358.88,3323.17 4764.47,3323.17 4771.88,3315.76 ; 4114.38,3459.92 4149.64,3459.92
XIN: C33.2 U1.30 U6.3 | length 758.2
  Top Layer w5: v1(4026.81,5669.16) 4041.65,5684.01 4085.76,5684.01 4100.61,5669.16 4104.76,5669.16 U1.30@4112.94,5660.98
  Inner2 w10: v1(4026.81,5669.16) 4026.81,5837.16 4050.81,5861.16 v1(4062.88,5861.16)
  Bottom Layer w10: C33.2@3986.88,5627.6 4026.81,5667.52 v1(4026.81,5669.16) ; v1(4062.88,5861.16) 4109.21,5861.16 4136.19,5888.15 4153.58,5888.15 4180.56,5861.16 4224.56,5861.16 4238.97,5875.57 4238.97,5916.02 U6.3@4337.57,6014.63
XOUT: R17.1 U1.31 | length 363.3
  Top Layer w9: U1.31@4124.07,5672.11 4136.24,5659.93 4136.24,5650.23 4134.95,5648.94 v1(4134.95,5636.3)
  Bottom Layer w10: v1(4134.95,5636.3) 4142.08,5636.3 R17.1@4364.68,5858.9
pads on no net: BMI270.2 BMI270.3 BMI270.9 BMI270.10 BMI270.11 BUZZER.2 BUZZER.4 STATUS.2 TF2.1 TF2.8 TF2.9 U1.8 U1.28 U1.33 U1.34 U1.36 U1.37 U1.47 U1.48 U1.56 U1.57 U1.58 U1.59 U1.68 U42.2 U43.7 U43.10 U43.13 U45.4 U45.6 U46.4 U47.4 USB1.3 USB1.9 USB1.13 USB1.14

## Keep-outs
Board Outline Layer:
  circle w10: c4576.88,6805.16 r59
  circle w10: c3414.88,6805.16 r59
  circle w10: c4576.88,3637.16 r59
  circle w10: c3414.88,3637.16 r59
  region: 3498.93,3637.16 cw(c3414.88,3637.16) 3330.84,3637.16 cw(c3414.88,3637.16)
  region: 4656.88,3637.16 cw(c4576.88,3637.16) 4496.88,3637.16 cw(c4576.88,3637.16)
  region: 4660.88,6805.16 cw(c4576.88,6805.16) 4492.88,6805.16 cw(c4576.88,6805.16)
  region: 3498.88,6805.16 cw(c3414.88,6805.16) 3330.88,6805.16 cw(c3414.88,6805.16)
  lines w10: 3006.88,3006.16 4975.38,3006.16 4975.38,6943.16 3006.88,6943.16 3006.88,3006.16

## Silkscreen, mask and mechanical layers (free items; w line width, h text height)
Top Silkscreen Layer:
  lines w3.94: 4100.16,4375.14 4141.56,4458.47 4182.95,4375.14 4141.88,4398.79 4141.56,4398.73 4141.24,4398.79 4100.16,4375.14 ; 4107.41,4382.85 4140.03,4401.63 4140.03,4448.51 4107.41,4382.85 ; 4143.09,4401.63 4143.09,4448.51 4175.7,4382.85 4143.09,4401.63
  text "GPIO" at 4798.88,6665.16 h80
  text "GPIO" at 3010.88,6657.16 h80
  text "26" at 4586.88,6541.16 h60
  text "06" at 3323.3,6510.33 h60
  text "Avian" at 3716.88,6493.16 h220
  text "07" at 3323.3,6329.64 h60
  text "25" at 4592.88,6323.16 h60
  text "08" at 3323.3,6122.86 h60
  text "24" at 4584.88,6119.16 h60
  text "23" at 4583.06,5939.92 h60
  text "09" at 3323.3,5919.99 h60
  text "ADC4" at 3328.88,4871.16 h60
  text "ADC2" at 4508.88,4865.16 h60
  text "ADC3" at 3328.88,4677.16 h60
  text "CS" at 4560.88,4661.16 h60
  text "RX" at 3332.88,4469.16 h60
  text "MOSI" at 4523.68,4454.61 h60
  text "CLK" at 4546.88,4271.16 h60
  text "TX" at 3337.3,4266.74 h60
  text "SCL" at 3330.88,4071.16 h60
  text "MISO" at 4522.87,4065.16 h60
  text "SDA" at 3334.88,3877.16 h60
  text "3.3V" at 4524.88,3865.16 h60
  text "36V" at 3840.88,3331.16 h60
  text "GND" at 4042.88,3329.16 h60
  text "P / W / M / 1" at 3371.89,3323.16 h60
  text "P / W / M / 2" at 3473.58,3316.16 h60
  text "P / W / M / 3" at 3573.27,3316.16 h60
  text "P / W / M / 4" at 3671.94,3316.16 h60
  text "P / W / M / 5" at 4274.95,3316.16 h60
  text "P / W / M / 6" at 4379.16,3315.76 h60
  text "P / W / M / 7" at 4479.35,3315.76 h60
  text "P / W / M / 8" at 4578.53,3315.76 h60
Bottom Silkscreen Layer:
  text "GND" at 4024.88,6809.16 h45
  text "36V" at 4130.88,6809.16 h45
  text "1.8V" at 4234.88,6809.16 h45
  text "3.3V" at 3834.88,6805.16 h45
  text "5V" at 3926.88,6805.16 h45
  text "GPIO" at 4831.1,6663.16 h80
  text "GPIO" at 3308.88,6657.16 h80
  text "26" at 4742.88,6533.16 h60
  text "06" at 3300.88,6511.16 h60
  text "07" at 3306.88,6323.16 h60
  text "25" at 4748.88,6317.16 h60
  text "08" at 3302.88,6127.16 h60
  text "24" at 4744.88,6111.16 h60
  text "23" at 4740.88,5933.16 h60
  text "09" at 3304.88,5923.16 h60 r270
  text "ADC4" at 3232.88,4935.16 h60
  text "ADC2" at 4908.88,4933.16 h60
  text "C43" at 3684.88,4769.16 h35 r90
  text "ADC3" at 3233.38,4745.16 h60
  text "CS" at 4866.88,4743.16 h60
  text "C45" at 3694.16,4627.59 h35 r90
  text "C44" at 3804.88,4623.16 h35 r270
  text "RX" at 3190.88,4551.16 h60
  text "MOSI" at 4894.88,4543.16 h60
  text "C46" at 3803.61,4490.61 h35 r270
  text "C47" at 3692.16,4489.3 h35 r90
  text "TX" at 3188.88,4353.16 h60
  text "CLK" at 4882.88,4349.16 h60
  text "SCL" at 3206.88,4155.16 h60
  text "MISO" at 4890.88,4151.16 h60
  text "SDA" at 3208.88,3957.16 h60
  text "3.3V" at 4892.88,3955.16 h60
  text "GND" at 3208.88,3761.16 h60
  text "GND" at 4884.88,3759.16 h60
  text "5V" at 3192.88,3567.16 h60
  text "5V" at 4866.88,3563.16 h60
  text "12V" at 3202.88,3367.16 h60
  text "12V" at 4876.88,3365.16 h60
  text "1" at 3393.66,3323.16 h60
  text "2" at 3504.92,3316.16 h60
  text "3" at 3604.1,3316.16 h60
  text "4" at 3706.3,3316.16 h60
  text "6" at 4407.61,3315.76 h60
  text "7" at 4498.73,3316.16 h60
  text "5" at 4304.9,3311.58 h60
  text "PYRO1" at 3230.88,3167.16 h60
  text "PYRO2" at 4926.88,3167.16 h60
  text "5V" at 4704.57,3133.47 h60
  text "5V" at 3326.88,3127.16 h60
  text "GND" at 4743.53,3035.07 h60
  text "GND" at 3336.89,3032.3 h60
